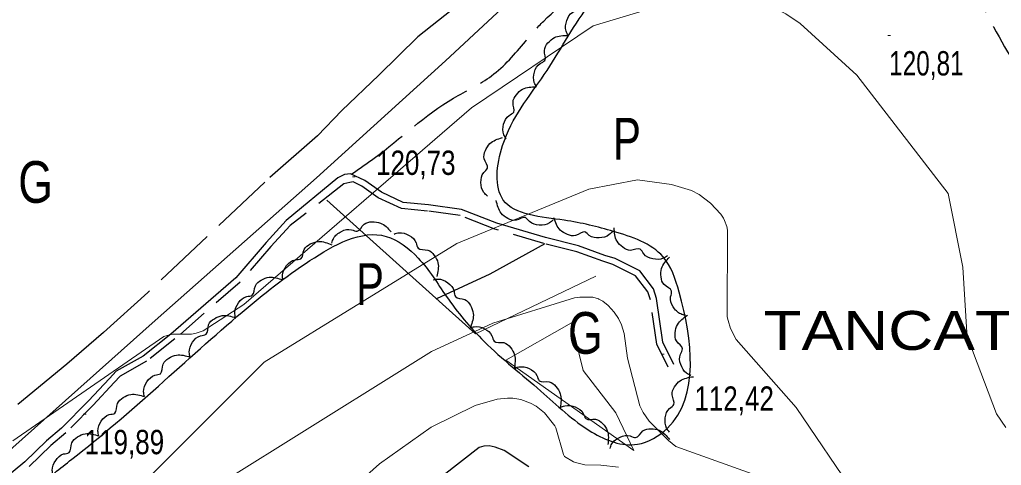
# Model space of a CAD drawing. Extents: x 483843 to 488449, y 4381269 to 4384483.
# Drawn here: x 484852.8 to 485206.3, y 4383726.9 to 4383887.3 of the extents above; entities that cross this region are included whole.
import ezdxf
from ezdxf.enums import TextEntityAlignment as Align

# ---------------------------------------------------------------- set-up
doc = ezdxf.new("R2010")
doc.units = 0
doc.header["$LTSCALE"] = 3.8
doc.linetypes.add('LONG_DASHED', pattern=[7.5, 6, -1.5])
doc.linetypes.add('MEDIUM_DASHED', pattern=[4.5, 3, -1.5])
for name, color, linetype, lineweight in [('25', 7, 'LONG_DASHED', 25), ('27', 7, 'Continuous', 25), ('38', 7, 'Continuous', 25), ('51', 7, 'Continuous', 13), ('7', 7, 'Continuous', 13), ('8', 7, 'Continuous', 25), ('9', 7, 'Continuous', 13)]:
    doc.layers.add(name, color=color, linetype=linetype, lineweight=lineweight)
doc.layers.add('31', color=7, linetype='Continuous')
doc.layers.add('5', color=7, linetype='Continuous')

msp = doc.modelspace()

# ---------------------------------------------------------------- linework, layer by layer
at = {"layer": '25'}
for points in [[(485011.06, 4383892.78), (484996.2, 4383881.13), (484982.1, 4383867.28), (484968.78, 4383854.62), (484959.97, 4383845.5), (484941.05, 4383828.82), (484898.88, 4383789.15), (484882.93, 4383774.74), (484869.72, 4383763.33), (484846.07, 4383743.72)], [(485041.84, 4383806.63), (485022.09, 4383795.68), (485002.85, 4383786.88)]]:
    msp.add_lwpolyline(points, dxfattribs=at)
at = {"layer": '27'}
for points in [[(484751.22, 4383489.34), (484756.51, 4383495.49), (484745.3, 4383535.28), (484742.64, 4383543.61), (484746.52, 4383557.62), (484756.05, 4383569.31), (484773.86, 4383582.26), (484787.94, 4383600.38), (484790.92, 4383606.81), (484801.14, 4383634.69), (484810.37, 4383651.59), (484815.95, 4383663.55), (484844.91, 4383701.14), (484865.32, 4383724.14), (484871.55, 4383729.12), (484932.91, 4383782.05), (484957.28, 4383800.57), (484984.73, 4383809.31), (484996.31, 4383801.48), (485006.38, 4383787.78), (485020.06, 4383771.48), (485040.43, 4383753.67), (485058.81, 4383738.92), (485075.21, 4383734.51), (485086.03, 4383740.33), (485090.23, 4383789.19), (485084.45, 4383801.97), (485066.61, 4383811.07), (485048.82, 4383815.11), (485026.93, 4383822.33), (485026.65, 4383841.93), (485041.68, 4383867.53), (485057.41, 4383891.99), (485077.46, 4383912.68), (485094.04, 4383927.94), (485104.64, 4383938.65), (485116.11, 4383941.78), (485127.04, 4383942.28), (485139.76, 4383948.55), (485137.99, 4383961.13), (485138.77, 4383978.1), (485148.32, 4383988.79), (485165.27, 4384013), (485164.63, 4384035.63), (485164.03, 4384041.23), (485165.37, 4384066.34), (485175.32, 4384086.85), (485185.76, 4384105.09), (485198.7, 4384128.93), (485200.81, 4384133.71)], [(485050.31, 4383881.51), (485049.55, 4383883.12), (485049.77, 4383886.9), (485051.93, 4383889.9), (485053.7, 4383890.95), (485053.73, 4383894.51), (485055.14, 4383897.13), (485057.56, 4383898.95), (485062.49, 4383899.48)], [(485038.94, 4383863.04), (485038.1, 4383864.6), (485038.14, 4383868.4), (485040.16, 4383871.49), (485041.87, 4383872.62), (485041.73, 4383876.18), (485043.02, 4383878.87), (485045.35, 4383880.8), (485050.25, 4383881.56)], [(485028, 4383844.3), (485027.12, 4383845.84), (485027.05, 4383849.63), (485028.98, 4383852.78), (485030.66, 4383853.96), (485030.42, 4383857.51), (485031.63, 4383860.24), (485033.9, 4383862.23), (485038.78, 4383863.13)], [(485021.2, 4383823.81), (485019.94, 4383825.06), (485018.87, 4383828.7), (485019.89, 4383832.25), (485021.19, 4383833.83), (485020.02, 4383837.19), (485020.47, 4383840.14), (485022.12, 4383842.67), (485026.59, 4383844.83)], [(485044.93, 4383815.3), (485043.59, 4383814.13), (485039.88, 4383813.33), (485036.42, 4383814.61), (485034.93, 4383816.03), (485031.5, 4383815.1), (485028.59, 4383815.76), (485026.19, 4383817.6), (485024.36, 4383822.22)], [(484965.22, 4383806.91), (484965.81, 4383808.58), (484968.65, 4383811.1), (484972.29, 4383811.69), (484974.28, 4383811.19), (484976.82, 4383813.68), (484979.68, 4383814.53), (484982.67, 4383814.11), (484986.53, 4383810.99)], [(485066.29, 4383811.21), (485065.08, 4383809.92), (485061.48, 4383808.73), (485057.9, 4383809.64), (485056.27, 4383810.9), (485052.96, 4383809.62), (485049.99, 4383809.97), (485047.41, 4383811.55), (485045.11, 4383815.95)], [(484987.62, 4383810.14), (484989.33, 4383810.59), (484993.01, 4383809.67), (484995.55, 4383806.98), (484996.25, 4383805.05), (484999.74, 4383804.36), (485002.05, 4383802.48), (485003.39, 4383799.76), (485002.98, 4383794.82)], [(485086.03, 4383802.36), (485084.53, 4383801.42), (485080.74, 4383801.21), (485077.52, 4383803.01), (485076.27, 4383804.64), (485072.74, 4383804.27), (485069.96, 4383805.37), (485067.88, 4383807.57), (485066.8, 4383812.41)], [(484947.57, 4383793.53), (484947.4, 4383795.3), (484948.9, 4383798.78), (484951.95, 4383800.86), (484953.97, 4383801.25), (484955.21, 4383804.58), (484957.44, 4383806.56), (484960.33, 4383807.45), (484965.14, 4383806.26)], [(485092.52, 4383780.92), (485090.8, 4383781.38), (485088.06, 4383784.01), (485087.19, 4383787.59), (485087.53, 4383789.62), (485084.84, 4383791.94), (485083.76, 4383794.73), (485083.94, 4383797.74), (485086.75, 4383801.84)], [(484930.5, 4383780.13), (484930.25, 4383781.89), (484931.6, 4383785.44), (484934.55, 4383787.65), (484936.55, 4383788.13), (484937.64, 4383791.52), (484939.77, 4383793.6), (484942.62, 4383794.62), (484947.48, 4383793.65)], [(485001.67, 4383793.72), (485003.43, 4383793.96), (485006.98, 4383792.61), (485009.18, 4383789.65), (485009.66, 4383787.65), (485013.04, 4383786.56), (485015.12, 4383784.42), (485016.13, 4383781.57), (485015.14, 4383776.7)], [(484914.16, 4383765.85), (484913.84, 4383767.6), (484915.04, 4383771.2), (484917.91, 4383773.53), (484919.88, 4383774.08), (484920.83, 4383777.51), (484922.88, 4383779.68), (484925.69, 4383780.81), (484930.59, 4383780.03)], [(485094.51, 4383759.29), (485092.93, 4383760.1), (485090.8, 4383763.23), (485090.69, 4383766.92), (485091.45, 4383768.83), (485089.31, 4383771.67), (485088.83, 4383774.62), (485089.64, 4383777.53), (485093.23, 4383780.95)], [(485014.75, 4383776.3), (485016.45, 4383776.82), (485020.17, 4383776.07), (485022.82, 4383773.51), (485023.62, 4383771.61), (485027.13, 4383771.08), (485029.53, 4383769.31), (485030.99, 4383766.66), (485030.82, 4383761.71)], [(484897.74, 4383751.66), (484897.42, 4383753.41), (484898.62, 4383757.01), (484901.49, 4383759.34), (484903.46, 4383759.9), (484904.41, 4383763.32), (484906.47, 4383765.49), (484909.27, 4383766.62), (484914.17, 4383765.84)], [(485030.85, 4383761.74), (485032.52, 4383762.33), (485036.27, 4383761.72), (485039.02, 4383759.25), (485039.88, 4383757.39), (485043.41, 4383756.99), (485045.88, 4383755.31), (485047.43, 4383752.71), (485047.44, 4383747.75)], [(485086.8, 4383738.89), (485085.75, 4383740.32), (485085.26, 4383744.08), (485086.82, 4383747.43), (485088.35, 4383748.79), (485087.71, 4383752.29), (485088.61, 4383755.14), (485090.64, 4383757.38), (485095.39, 4383758.82)], [(484881.29, 4383737.51), (484880.98, 4383739.26), (484882.18, 4383742.85), (484885.05, 4383745.18), (484887.03, 4383745.73), (484887.98, 4383749.16), (484890.04, 4383751.32), (484892.85, 4383752.45), (484897.74, 4383751.66)], [(485047.42, 4383747.73), (485049.07, 4383748.39), (485052.84, 4383747.93), (485055.69, 4383745.59), (485056.63, 4383743.76), (485060.17, 4383743.5), (485062.71, 4383741.92), (485064.37, 4383739.4), (485064.58, 4383734.44)], [(484864.85, 4383723.35), (484864.53, 4383725.1), (484865.74, 4383728.69), (484868.61, 4383731.02), (484870.58, 4383731.57), (484871.54, 4383735), (484873.6, 4383737.16), (484876.4, 4383738.29), (484881.3, 4383737.5)], [(485065.36, 4383733.01), (485066.02, 4383734.66), (485068.95, 4383737.07), (485072.62, 4383737.51), (485074.59, 4383736.93), (485077.22, 4383739.33), (485080.11, 4383740.07), (485083.08, 4383739.53), (485086.82, 4383736.27)]]:
    msp.add_spline(points, degree=3, dxfattribs=at)
at = {"layer": '38'}
msp.add_lwpolyline([(485088.37, 4383763.24), (485084.4, 4383771.26), (485082.09, 4383786.98), (485081.05, 4383790.44), (485076.06, 4383796.86), (485067.19, 4383801.29), (485063.52, 4383802.47), (485054.02, 4383805.87), (485042.14, 4383808.88), (485024.6, 4383814.06), (485011.93, 4383819.01), (484999.94, 4383820.66), (484990.86, 4383821.5), (484983.01, 4383825.16), (484977.01, 4383829.42), (484971.94, 4383831.85), (484969.78, 4383831.53), (484967.3, 4383830.32), (484948.71, 4383814.99), (484941.51, 4383807.14), (484930.58, 4383794.42), (484907.22, 4383774.17), (484897.23, 4383766.26), (484887.51, 4383760.8), (484885.11, 4383758.22), (484877.62, 4383750.09), (484867.89, 4383740.29), (484862.47, 4383735.79), (484854.64, 4383728.2), (484838.48, 4383714.93)], dxfattribs=at)
at = {"layer": '38', "linetype": 'MEDIUM_DASHED'}
msp.add_lwpolyline([(485086.34, 4383762.24), (485082.21, 4383770.58), (485079.88, 4383786.49), (485079.01, 4383789.39), (485074.59, 4383795.07), (485066.34, 4383799.19), (485062.79, 4383800.33), (485053.36, 4383803.71), (485041.55, 4383806.7), (485023.87, 4383811.92), (485011.36, 4383816.81), (484999.68, 4383818.41), (484990.27, 4383819.29), (484981.87, 4383823.19), (484975.95, 4383827.4), (484972.83, 4383828.92), (484971.69, 4383828.73), (484969.46, 4383828.16), (484950.16, 4383813.22), (484943.2, 4383805.64), (484932.19, 4383792.82), (484908.67, 4383772.43), (484898.49, 4383764.38), (484888.92, 4383759.01), (484886.77, 4383756.69), (484879.25, 4383748.53), (484869.42, 4383738.62), (484863.98, 4383734.11), (484856.15, 4383726.52)], dxfattribs=at)
at = {"layer": '38', "linetype": 'LONG_DASHED'}
msp.add_spline([(484972.26, 4383831.7), (484980.43, 4383837.4), (485008.98, 4383859.02), (485022.72, 4383867.06), (485034.88, 4383879.41), (485041.47, 4383886.77), (485063.96, 4383905.64), (485074.39, 4383917.53), (485084.6, 4383933.27), (485091.17, 4383940.62), (485127.43, 4383955.12), (485178.77, 4383930.53), (485187.47, 4383919.86), (485199, 4383893.86), (485214.72, 4383865.18), (485220.2, 4383854.96), (485234.5, 4383822.77), (485238.17, 4383819.28), (485268.15, 4383804.36), (485263.11, 4383804.76), (485253.69, 4383806.59)], degree=3, dxfattribs=at)
at = {"layer": '51'}
for points in [[(485191.03, 4384133.73), (485185.05, 4384122.02), (485178.17, 4384110.09), (485159.79, 4384086.89), (485148.24, 4384074.66), (485159.64, 4384019.73), (485146.63, 4384006.97), (485127.72, 4383988.39), (485100.9, 4383960.59), (485006.16, 4383872.43), (484959.71, 4383830.34)], [(484959.71, 4383830.34), (484901.62, 4383778.99), (484810.16, 4383697.57), (484728.36, 4383793.32)], [(485060.2, 4383794.95), (485016.86, 4383774.28), (484963.33, 4383822.37)]]:
    msp.add_lwpolyline(points, dxfattribs=at)
msp.add_lwpolyline([(485067.49, 4383745.84), (485073.89, 4383732.25), (485027.84, 4383764.79), (485051.49, 4383778.24), (485055.73, 4383761.03)], close=True, dxfattribs=at)
at = {"layer": '7'}
for p, q in [((485165.35, 4383881.55), (485166.35, 4383881.55)), ((484972.57, 4383830.71), (484973.57, 4383830.71)), ((485083.82, 4383766.94), (485084.82, 4383766.94)), ((484875.67, 4383745.31), (484876.67, 4383745.31))]:
    msp.add_line(p, q, dxfattribs=at)
at = {"layer": '8'}
msp.add_lwpolyline([(485036.1, 4383726.35), (485027.2, 4383732.25), (485024.05, 4383733.53), (485021.84, 4383733.93), (485019.87, 4383733.84), (485018.19, 4383733.4), (484991.03, 4383712.11)], dxfattribs=at)
at = {"layer": '9'}
for points in [[(484850.28, 4383735.72), (484904.71, 4383773.23), (484906.7, 4383773.88), (484907.91, 4383774.08), (484914.65, 4383774.12), (484916.33, 4383774.43), (484918.82, 4383775.35), (484933.53, 4383784.81), (485015.43, 4383855.58), (485059.26, 4383885.05), (485092.92, 4383895.28), (485096.5, 4383895.66), (485113.58, 4383895.2), (485116.52, 4383894.55), (485121.19, 4383893.05), (485128.71, 4383889.39), (485133.77, 4383885.83), (485154.23, 4383867.32), (485187.07, 4383824.75), (485192.34, 4383798.19), (485193.79, 4383774.68), (485194.57, 4383771.76), (485204.53, 4383745.52), (485207.83, 4383740.53)], [(484880.51, 4383703.91), (484940.79, 4383764.06), (485010.2, 4383806.73), (485057.77, 4383826.27), (485075.22, 4383829.67), (485087.53, 4383827.95), (485094.73, 4383825.8), (485097.48, 4383824.42), (485101.48, 4383821.29), (485105.22, 4383817.29), (485106.18, 4383815.84), (485106.59, 4383815.01), (485107.36, 4383812.84), (485107.63, 4383811.48), (485107.55, 4383780.38), (485107.84, 4383778.99), (485108.75, 4383776.19), (485110.78, 4383772.19), (485132.4, 4383747.7), (485153.91, 4383716.13)], [(485119.54, 4383722.84), (485089.09, 4383733.76), (485086.38, 4383735.89), (485079.47, 4383742.77), (485077.24, 4383745.93), (485076.13, 4383748.33), (485071.61, 4383765.54), (485070.48, 4383774.33), (485069.51, 4383777.47), (485068.36, 4383779.81), (485066.79, 4383782.08), (485064.72, 4383784.45), (485064.7, 4383784.46), (485062.81, 4383785.95), (485061.36, 4383786.76), (485061.18, 4383786.82), (485059.18, 4383787.41), (485054.48, 4383787.47), (485054.44, 4383787.48), (485052.59, 4383787.22), (485023.1, 4383778.04), (485001.06, 4383767.92), (484989.5, 4383760.73)], [(484989.5, 4383760.73), (484924.99, 4383720.42)], [(485068.38, 4383726.27), (485061.99, 4383727.05), (485056.29, 4383727.17), (485052.88, 4383727.99), (485052.17, 4383728.23), (485048.95, 4383730.15), (485048.56, 4383730.79), (485045.86, 4383740.46), (485045.54, 4383741.2), (485041.75, 4383745.86), (485038.81, 4383748.18), (485036.68, 4383749.34), (485033.2, 4383750.59), (485030.3, 4383751.06), (485028.48, 4383751.13), (485024.75, 4383750.77), (485016.8, 4383748.42), (485000.93, 4383740.62), (484982.32, 4383727.5), (484952.54, 4383700.89)]]:
    msp.add_lwpolyline(points, dxfattribs=at)

# ---------------------------------------------------------------- texts
at = {"layer": '31'}
for s, width, p in [('P', 0.75, (485071.47, 4383836.9)), ('G', 0.8, (484858.51, 4383821.37)), ('P', 0.75, (484978.94, 4383784.65)), ('G', 0.8, (485056.47, 4383767.07))]:
    msp.add_text(s, height=15, dxfattribs=dict(at, width=width)).set_placement(p, align=Align.CENTER)
at = {"layer": '5', "width": 1.2}
msp.add_text('TANCAT DES OLLERS', height=14, dxfattribs=at).set_placement((485120.61, 4383768.46))
at = {"layer": '7'}
for s, width, p in [('120,81', 0.75, (485165.85, 4383867.18)), ('120,73', 0.8, (484981.09, 4383831.41)), ('112,42', 0.8, (485095.73, 4383746.57)), ('119,89', 0.8, (484876.17, 4383730.94))]:
    msp.add_text(s, height=8.75, dxfattribs=dict(at, width=width)).set_placement(p)

doc.saveas('drawing.dxf')
